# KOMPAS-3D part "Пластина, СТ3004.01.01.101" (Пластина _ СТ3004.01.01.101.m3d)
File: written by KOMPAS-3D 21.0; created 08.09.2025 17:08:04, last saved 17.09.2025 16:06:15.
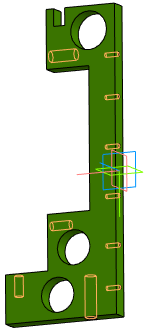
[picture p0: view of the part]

Document properties: Полное имя файла: C:\Users\Lutik\Yandex.Disk\Документы\Новая папка\Стапель №2\Стапель _ СТ3004.00.00.000\Опора _ СТ3004.01.00.000\3D\Кронштейн _ СТ3004.01.01.000\Основание _ СТ3004.01.01.100\Пластина _ СТ3004.01.01.101.m3d

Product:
- Part/product: Пластина  | designation СТ3004.01.01.101
    Материал: Лист$dБ-ПН-НО-25 ГОСТ 19903-2015;Ст3сп ГОСТ 14637-89$ (density 7850 kg/m3)
    Масса: 5.762144
    Форматы листов документа: A2

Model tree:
1. Эскиз:1
2. Элемент выдавливания:1
     Расстояние 1 = 25
3. Эскиз:84  (with: Элемент выдавливания:1)
4. ЛСК:59  (with: Плоскость XY, Плоскость ZX, Плоскость ZY, Ось X, Ось Y, Ось Z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)
     Ось X. X = -1; Ось Y. Y = 1; Ось Z. Z = -1; Координата Y = -35; Точка начала. Y = -35
5. Эскиз:85
6. Элемент вращения:19
     Угол 1 = 360
7. Смещенная плоскость:18  (with: Элемент выдавливания:1)
     Расстояние = 0.458734
8. Условное изображение резьбы:20  (with: Элемент вращения:19)  (labels: 6x1)
     Длина резьбы = 19.5413; Шаг резьбы = 1; Номинальный диаметр резьбы = 6
9. Подгонка:1
10. Отверстие М6x20-25/1x45°
11. Эскиз:87  (with: Элемент выдавливания:1)
12. ЛСК:61  (with: Плоскость XY, Плоскость ZX, Плоскость ZY, Ось X, Ось Y, Ось Z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)
     Ось X. X = -1; Ось Y. Y = 1; Ось Z. Z = -1; Координата Y = -105; Точка начала. Y = -105
13. Эскиз:88
14. Элемент вращения:20
     Угол 1 = 360
15. Смещенная плоскость:19  (with: Элемент выдавливания:1)
     Расстояние = 0.458734
16. Условное изображение резьбы:21  (with: Элемент вращения:20)  (labels: 6x1)
     Длина резьбы = 19.5413; Шаг резьбы = 1; Номинальный диаметр резьбы = 6
17. Подгонка:2
18. Отверстие М6x20-25/1x45° (1)
19. Эскиз:90  (with: Элемент выдавливания:1)
20. ЛСК:63  (with: Плоскость XY, Плоскость ZX, Плоскость ZY, Ось X, Ось Y, Ось Z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)
     Ось X. X = -1; Ось Y. Y = 1; Ось Z. Z = -1; Координата Y = -165; Точка начала. Y = -165
21. Эскиз:91
22. Элемент вращения:21
     Угол 1 = 360
23. Смещенная плоскость:20  (with: Элемент выдавливания:1)
     Расстояние = 0.458734
24. Условное изображение резьбы:22  (with: Элемент вращения:21)  (labels: 6x1)
     Длина резьбы = 19.5413; Шаг резьбы = 1; Номинальный диаметр резьбы = 6
25. Подгонка:3
26. Отверстие М6x20-25/1x45° (2)
27. Эскиз:93  (with: Элемент выдавливания:1)
28. ЛСК:65  (with: Плоскость XY, Плоскость ZX, Плоскость ZY, Ось X, Ось Y, Ось Z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)
     Ось X. X = -1; Ось Y. Y = 1; Ось Z. Z = -1; Координата Y = 35; Точка начала. Y = 35
29. Эскиз:94
30. Элемент вращения:22
     Угол 1 = 360
31. Смещенная плоскость:21  (with: Элемент выдавливания:1)
     Расстояние = 0.458734
32. Условное изображение резьбы:23  (with: Элемент вращения:22)  (labels: 6x1)
     Длина резьбы = 19.5413; Шаг резьбы = 1; Номинальный диаметр резьбы = 6
33. Подгонка:4
34. Отверстие М6x20-25/1x45° (3)
35. Эскиз:96  (with: Элемент выдавливания:1)
36. ЛСК:67  (with: Плоскость XY, Плоскость ZX, Плоскость ZY, Ось X, Ось Y, Ось Z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)
     Ось X. X = -1; Ось Y. Y = 1; Ось Z. Z = -1; Координата Y = 105; Точка начала. Y = 105
37. Эскиз:97
38. Элемент вращения:23
     Угол 1 = 360
39. Смещенная плоскость:22  (with: Элемент выдавливания:1)
     Расстояние = 0.458734
40. Условное изображение резьбы:24  (with: Элемент вращения:23)  (labels: 6x1)
     Длина резьбы = 19.5413; Шаг резьбы = 1; Номинальный диаметр резьбы = 6
41. Подгонка:5
42. Отверстие М6x20-25/1x45° (4)
43. Эскиз:99  (with: Элемент выдавливания:1)
44. ЛСК:69  (with: Плоскость XY, Плоскость ZX, Плоскость ZY, Ось X, Ось Y, Ось Z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)
     Ось X. X = -1; Ось Y. Y = 1; Ось Z. Z = -1; Координата Y = 165; Точка начала. Y = 165
45. Эскиз:100
46. Элемент вращения:24
     Угол 1 = 360
47. Смещенная плоскость:23  (with: Элемент выдавливания:1)
     Расстояние = 0.458734
48. Условное изображение резьбы:25  (with: Элемент вращения:24)  (labels: 6x1)
     Длина резьбы = 19.5413; Шаг резьбы = 1; Номинальный диаметр резьбы = 6
49. Подгонка:6
50. Отверстие М6x20-25/1x45° (5)
51. Эскиз:103  (with: Элемент выдавливания:1)
52. ЛСК:72  (with: Плоскость XY, Плоскость ZX, Плоскость ZY, Ось X, Ось Y, Ось Z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)
     Ось X. X = 1; Ось Y. Y = 1; Ось Z. Z = 1; Координата X = 105; Координата Y = -170; Точка начала. Х = 105; Точка начала. Y = -170
53. Эскиз:104
54. Элемент вращения:25
     Угол 1 = 360
55. Смещенная плоскость:24  (with: Элемент выдавливания:1)
     Расстояние = 0.917468
56. Условное изображение резьбы:26  (with: Элемент вращения:25)  (labels: 16x2)
     Длина резьбы = 39.0825; Шаг резьбы = 2; Номинальный диаметр резьбы = 16
57. Подгонка:7
58. Отверстие М16x40-45/2x45°
59. Эскиз:107  (with: Элемент выдавливания:1)
60. ЛСК:75  (with: Плоскость XY, Плоскость ZX, Плоскость ZY, Ось X, Ось Y, Ось Z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)
     Ось X. Y = 1; Ось Y. X = 1; Ось Z. Z = -1; Координата X = 45; Координата Y = 205; Точка начала. Х = 45; Точка начала. Y = 205
61. Эскиз:108
62. Элемент вращения:26
     Угол 1 = 360
63. Смещенная плоскость:25  (with: Элемент выдавливания:1)
     Расстояние = 0.917468
64. Условное изображение резьбы:27  (with: Элемент вращения:26)  (labels: 16x2)
     Длина резьбы = 59.0825; Шаг резьбы = 2; Номинальный диаметр резьбы = 16
65. Подгонка:8
66. Отверстие М16x60-65/2x45°
67. Эскиз:112  (with: Элемент выдавливания:1)
68. ЛСК:79  (with: Плоскость XY, Плоскость ZX, Плоскость ZY, Ось X, Ось Y, Ось Z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)
     Ось X. Y = -1; Ось Y. X = 1; Ось Z. Z = 1; Координата X = 155; Координата Y = 135; Точка начала. Х = 155; Точка начала. Y = 135
69. Эскиз:113
70. Элемент вращения:27
     Угол 1 = 360
71. Смещенная плоскость:26  (with: Элемент выдавливания:1)
     Расстояние = 0.652785
72. Условное изображение резьбы:28  (with: Элемент вращения:27)  (labels: 12x1,75)
     Длина резьбы = 29.3472; Шаг резьбы = 1.75; Номинальный диаметр резьбы = 12
73. Подгонка:9
74. Отверстие М12x30-35/1,6x45°
75. Эскиз:116  (with: Элемент выдавливания:1)
76. ЛСК:82  (with: Плоскость XY, Плоскость ZX, Плоскость ZY, Ось X, Ось Y, Ось Z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)
     Ось X. X = 1; Ось Y. Y = 1; Ось Z. Z = 1; Координата X = 105; Координата Y = 70; Точка начала. Х = 105; Точка начала. Y = 70
77. Эскиз:117
78. Элемент вращения:28
     Угол 1 = 360
79. Смещенная плоскость:27  (with: Элемент выдавливания:1)
     Расстояние = 0.652785
80. Условное изображение резьбы:29  (with: Элемент вращения:28)  (labels: 12x1,75)
     Длина резьбы = 29.3472; Шаг резьбы = 1.75; Номинальный диаметр резьбы = 12
81. Подгонка:10
82. Отверстие М12x30-35/1,6x45° (1)
83. Эскиз:124  (with: Элемент выдавливания:1)
84. ЛСК:88  (with: Плоскость XY, Плоскость ZX, Плоскость ZY, Ось X, Ось Y, Ось Z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)
     Ось X. X = 1; Ось Y. Y = 1; Ось Z. Z = 1; Координата X = 170; Координата Y = 190; Точка начала. Х = 170; Точка начала. Y = 190
85. Эскиз:125
86. Присоединительная точка:3
     Перенос X = -10; Расстояние = -10
87. Элемент вращения:30
     Угол 1 = 360
88. Отверстие Ф16x35/2x45°
89. Эскиз:126  (with: Элемент выдавливания:1)
90. Элемент выдавливания:6  (labels: Лист$dБ-ПН-НО-25 ГОСТ 19903-2015;Ст3сп ГОСТ 14637-89$)
     Расстояние 2 = 25

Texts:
  KTE.LIST=LTWD36N5dmSErgwNQxupvb
  KTE.LIST=f.sO0tLtictm5WUlIlwVlc
  Edge1
  Edge2
  СТ3004.01.01.101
